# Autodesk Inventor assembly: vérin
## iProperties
Shininess: 59.0
Length Units: 11269
Angle Units: 11279
Time Units: 11290
Mass Units: 11283
Length Display Precision: 3
Angle Display Precision: 2
Created: 2002-06
Part Number: vérin
Document SubType Name: Assemblage
Designer: REVEST Pierre
Density: 0.0
Volumn: 0.0
Area: 0.0
PropertySet Name: Model Information
Control State: 0
Master: False
Checked Out: False
Author: REVEST Pierre
